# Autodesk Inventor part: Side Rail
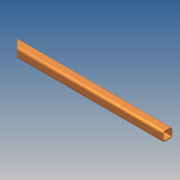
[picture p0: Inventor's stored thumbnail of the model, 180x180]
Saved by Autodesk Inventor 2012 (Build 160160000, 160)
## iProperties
Created: 2007-12
Part Number: Side Rail
Document SubType Name: Modeling
Designer: MJ
Material: Aluminum-6061
Stock Number: D-623-012-c
Density: 2.71 g/cm^3
Engineer: MJ
Mass: 1623.06 g
Surface Area: 1911.1 cm^2
Volume: 598.917 cm^3
RuleStatus: InUse
Title: DgPr Assembly Cell
Author: MJ
Comments: 1.50" X 1.50" X 1/8" WALL TUBE X 46"
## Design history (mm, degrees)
sketch "Sketch2"
  geometry: L1 (-12.7, -25.4)-(12.7, -25.4); L2 (25.4, -12.7)-(25.4, 12.7); L3 (12.7, 25.4)-(-12.7, 25.4); L4 (-25.4, 12.7)-(-25.4, -12.7); L5 (-19.05, 12.7)-(-19.05, -12.7); L6 (-12.7, -19.05)-(12.7, -19.05); L7 (19.05, -12.7)-(19.05, 12.7); L8 (12.7, 19.05)-(-12.7, 19.05); A1 r 12.7 centre (12.7, 12.7) between (25.4, 12.7) and (12.7, 25.4); A2 r 12.7 centre (-12.7, 12.7) between (-12.7, 25.4) and (-25.4, 12.7); A3 r 12.7 centre (-12.7, -12.7) between (-25.4, -12.7) and (-12.7, -25.4); A4 r 12.7 centre (12.7, -12.7) between (12.7, -25.4) and (25.4, -12.7); A5 r 6.35 centre (-12.7, 12.7) between (-12.7, 19.05) and (-19.05, 12.7); A6 r 6.35 centre (-12.7, -12.7) between (-19.05, -12.7) and (-12.7, -19.05); A7 r 6.35 centre (12.7, -12.7) between (12.7, -19.05) and (19.05, -12.7); A8 r 6.35 centre (12.7, 12.7) between (19.05, 12.7) and (12.7, 19.05); 6 further points
  constraints: 16 end point, 16 point on circle, 8 centre point, 8 tangent, 6 point on line, 5 parallel, 3 equal radius, 2 horizontal alignment, 2 midpoint, 2 perpendicular, 2 vertical alignment, 1 horizontal, 8 other
extrude "Extrusion1" new body sketch "Sketch2" taper "d5" = 0 deg
sketch "Sketch3"
  geometry: L1 (25.4, 609.6)-(0, 609.6) reference; L2 (38.1, 609.6)-(38.1, 0) reference; L3 (-12.7, 609.6)-(0, 609.6) reference; L4 (-12.7, 609.6)-(-12.7, 0) reference; L5 (25.4, 609.6)-(38.1, 609.6) reference; L6 (38.1, 609.6)-(-12.7, 558.8); 1 further point
  constraints: 2 end point, 1 point on line
  dimensions: "TubeEndAngle" = 45 deg angle of L3 L6
extrude "Extrusion2" cut sketch "Sketch3" stored distance "d7" = 25.4; taper "d8" = 0 deg
body "Solid1"
